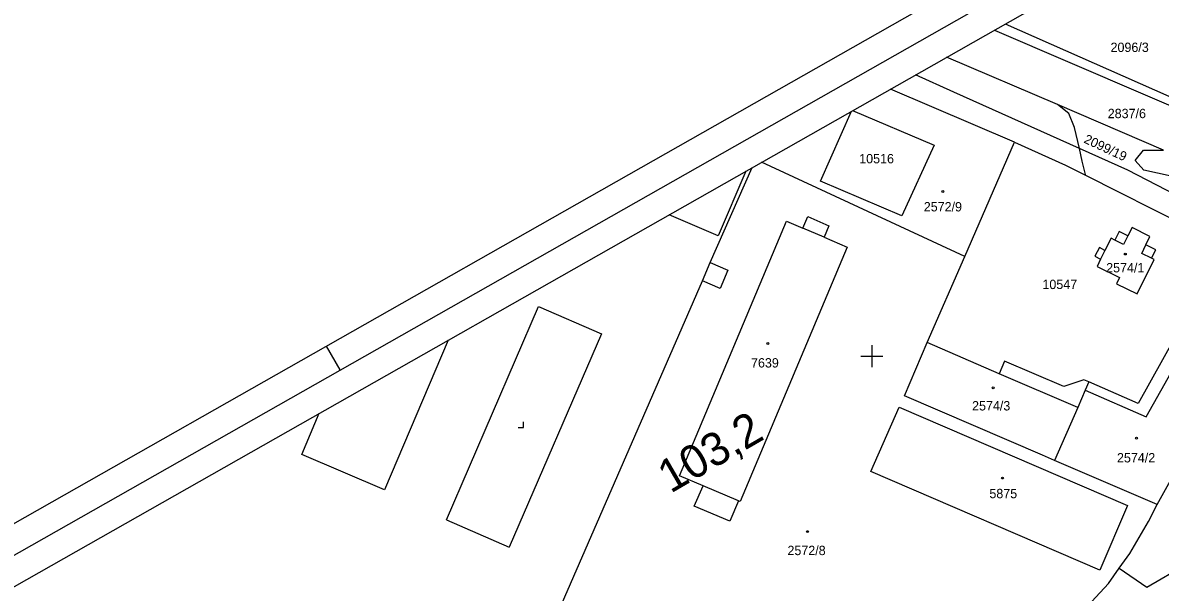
# Model space of a CAD drawing. Extents: x -566165 to -565287, y -1203064 to -1202391.
# Drawn here: x -565854.5 to -565647.5, y -1202643 to -1202539.4 of the extents above; entities that cross this region are included whole.
import ezdxf

# ---------------------------------------------------------------- set-up
doc = ezdxf.new("R2010")
doc.units = 0
for name, color, linetype in [('Hranice parcel', 7, 'Continuous'), ('Parcelní čísla', 7, 'Continuous'), ('Vnitřní kresba', 7, 'Continuous'), ('Vrstva 1', 7, 'Continuous'), ('Vrstva 5', 7, 'Continuous'), ('Vrstva 7', 7, 'Continuous'), ('Značky budov', 7, 'Continuous'), ('Značky kultur', 7, 'Continuous')]:
    doc.layers.add(name, color=color, linetype=linetype)

msp = doc.modelspace()

# ---------------------------------------------------------------- linework, layer by layer
at = {"layer": 'Hranice parcel'}
for p, q in [((-565675.68, -1202539.58), (-565645.92, -1202552.72)), ((-565674, -1202561.11), (-565696.58, -1202551.43)), ((-565662.2, -1202562.24), (-565685.03, -1202551.98)), ((-565646.9, -1202562.53), (-565666.21, -1202554.22)), ((-565709.33, -1202568.19), (-565703.68, -1202555.46)), ((-565662.2, -1202562.24), (-565663.08, -1202558.41)), ((-565683.07, -1202581.87), (-565674, -1202561.11)), ((-565674, -1202561.11), (-565664.72, -1202565.27)), ((-565661.67, -1202564.55), (-565662.2, -1202562.24)), ((-565653.37, -1202566.21), (-565662.2, -1202562.24)), ((-565683.07, -1202581.87), (-565720.05, -1202564.75)), ((-565729.37, -1202583), (-565721.74, -1202565.71)), ((-565722.89, -1202566.36), (-565727.95, -1202578.11)), ((-565664.72, -1202565.27), (-565661.08, -1202567.11)), ((-565661.08, -1202567.11), (-565661.11, -1202566.99)), ((-565626.76, -1202580.01), (-565653.37, -1202566.21)), ((-565661.08, -1202567.11), (-565633.3, -1202581.16)), ((-565689.92, -1202597.55), (-565683.07, -1202581.87)), ((-565649.94, -1202642), (-565590.75, -1202607.97)), ((-565648.07, -1202626.98), (-565641.33, -1202614.86)), ((-565666.73, -1202618.97), (-565668.89, -1202618.04)), ((-565648.07, -1202626.98), (-565666.73, -1202618.97)), ((-565654.95, -1202638.6), (-565653.02, -1202635.92)), ((-565656.92, -1202641.34), (-565654.95, -1202638.6)), ((-565654.95, -1202638.6), (-565649.94, -1202642))]:
    msp.add_line(p, q, dxfattribs=at)
for points in [[(-565677.65, -1202540.7), (-565636.53, -1202558.35)], [(-565666.21, -1202554.22), (-565686.4, -1202545.66)], [(-565685.03, -1202551.98), (-565692.02, -1202548.85)], [(-565663.08, -1202558.41), (-565664.13, -1202555.88), (-565666.21, -1202554.22)], [(-565703.5, -1202555.36), (-565688.64, -1202561.63), (-565694.52, -1202574.52), (-565709.33, -1202568.19)], [(-565611.48, -1202587.61), (-565606.37, -1202588.55), (-565605.02, -1202584.84), (-565609.5, -1202583.94), (-565619.91, -1202582.67), (-565618.87, -1202580.59), (-565643.02, -1202567.83), (-565650.49, -1202566.2), (-565652.02, -1202564.43), (-565650.55, -1202562.52), (-565646.9, -1202562.53)], [(-565661.11, -1202566.99), (-565661.23, -1202566.5), (-565661.67, -1202564.55)], [(-565727.95, -1202578.11), (-565736.87, -1202574.29)], [(-565715.53, -1202575.44), (-565712.53, -1202576.72), (-565711.64, -1202574.64), (-565707.77, -1202576.29), (-565708.67, -1202578.37), (-565704.44, -1202580.18), (-565723.91, -1202626.46), (-565724.22, -1202626.33), (-565725.81, -1202630.05), (-565732.28, -1202627.29), (-565730.69, -1202623.57), (-565734.96, -1202621.75), (-565715.53, -1202575.44)], [(-565658.99, -1202583.69), (-565654.89, -1202585.73), (-565655.44, -1202586.84), (-565651.71, -1202588.69), (-565648.61, -1202582.44), (-565649.07, -1202582.21), (-565648.3, -1202580.67), (-565650.11, -1202579.77), (-565649.38, -1202578.26), (-565652.62, -1202576.61), (-565653.38, -1202578.15), (-565654.99, -1202577.35), (-565655.76, -1202578.89), (-565656.44, -1202578.55), (-565657.54, -1202580.77)], [(-565633.3, -1202581.16), (-565640.46, -1202593.97), (-565642.65, -1202592.75), (-565651.52, -1202608.61), (-565660.47, -1202604.69)], [(-565657.54, -1202580.77), (-565658.57, -1202580.25), (-565659.37, -1202581.85), (-565658.33, -1202582.36), (-565658.99, -1202583.69)], [(-565758.54, -1202649.93), (-565730.78, -1202586.31), (-565729.37, -1202583)], [(-565777.1, -1202597.11), (-565788.65, -1202624.32), (-565803.71, -1202617.93), (-565800.53, -1202610.4)], [(-565668.89, -1202618.04), (-565694.05, -1202607.23), (-565689.92, -1202597.55)], [(-565675.81, -1202600.91), (-565676.8, -1202603.2), (-565689.92, -1202597.55)], [(-565660.47, -1202604.69), (-565661.37, -1202604.3), (-565665.05, -1202605.56), (-565675.81, -1202600.91)], [(-565660.47, -1202604.69), (-565661.13, -1202606.2), (-565662.51, -1202609.35), (-565666.73, -1202618.97)], [(-565700.13, -1202620.97), (-565695.02, -1202609.31), (-565653.44, -1202627.2)], [(-565653.44, -1202627.2), (-565658.48, -1202638.91), (-565700.13, -1202620.97)], [(-565653.02, -1202635.92), (-565649.64, -1202630.11), (-565648.07, -1202626.98)], [(-565674.56, -1202656.97), (-565671.65, -1202655.14), (-565668.84, -1202653.22), (-565663.79, -1202648.82), (-565656.92, -1202641.34)]]:
    msp.add_lwpolyline(points, dxfattribs=at)
at = {"layer": 'Vnitřní kresba'}
for p, q in [((-565708.67, -1202578.37), (-565712.53, -1202576.72)), ((-565654.15, -1202579.69), (-565655.76, -1202578.89)), ((-565653.38, -1202578.15), (-565654.15, -1202579.69)), ((-565657.54, -1202580.77), (-565658.33, -1202582.36)), ((-565650.86, -1202581.32), (-565650.11, -1202579.77)), ((-565649.07, -1202582.21), (-565650.86, -1202581.32)), ((-565729.37, -1202583), (-565726.16, -1202584.37)), ((-565726.16, -1202584.37), (-565727.57, -1202587.68)), ((-565727.57, -1202587.68), (-565730.78, -1202586.31)), ((-565777.39, -1202629.8), (-565760.61, -1202590.98)), ((-565760.61, -1202590.98), (-565749.16, -1202595.94)), ((-565749.16, -1202595.94), (-565765.95, -1202634.75)), ((-565650.02, -1202611.06), (-565640.46, -1202593.97)), ((-565662.51, -1202609.35), (-565676.8, -1202603.2)), ((-565661.13, -1202606.2), (-565650.02, -1202611.06)), ((-565724.22, -1202626.33), (-565730.69, -1202623.57)), ((-565777.39, -1202629.8), (-565765.95, -1202634.75))]:
    msp.add_line(p, q, dxfattribs=at)
at = {"layer": 'Vrstva 1'}
msp.add_line((-565796.76, -1202602.52), (-565799.23, -1202598.18), dxfattribs=at)
for points in [[(-566017.99, -1203063.73), (-565287.38, -1202649.25), (-565433.92, -1202390.94), (-566164.53, -1202805.42)], [(-565294.2, -1202647.37), (-566016.11, -1203056.92), (-566157.72, -1202807.3), (-565435.81, -1202397.75)], [(-566014.23, -1203050.11), (-565479.31, -1202746.65), (-565615.99, -1202505.72), (-566150.91, -1202809.18)]]:
    msp.add_lwpolyline(points, close=True, dxfattribs=at)
at = {"layer": 'Vrstva 5'}
for p, q in [((-565700, -1202598), (-565700, -1202602)), ((-565702, -1202600), (-565698, -1202600))]:
    msp.add_line(p, q, dxfattribs=at)
at = {"layer": 'Značky budov'}
for centre in [(-565687.03, -1202570.09), (-565653.84, -1202581.44), (-565718.89, -1202597.73), (-565677.91, -1202605.79), (-565651.79, -1202614.92), (-565676.21, -1202622.18), (-565711.68, -1202631.93)]:
    msp.add_circle(centre, 0.175, dxfattribs=at)
at = {"layer": 'Značky kultur'}
for p, q in [((-565763.36, -1202612.96), (-565763.36, -1202611.96)), ((-565764.36, -1202612.96), (-565763.36, -1202612.96))]:
    msp.add_line(p, q, dxfattribs=at)

# ---------------------------------------------------------------- texts
at = {"layer": 'Parcelní čísla'}
for s, p in [('2096/3', (-565656.53, -1202544.69)), ('2837/6', (-565657.04, -1202556.73)), ('10516', (-565702.27, -1202564.94)), ('2572/9', (-565690.52, -1202573.69)), ('2574/1', (-565657.33, -1202584.78)), ('10547', (-565668.93, -1202587.81)), ('7639', (-565721.96, -1202602.08)), ('2574/3', (-565681.73, -1202609.89)), ('2574/2', (-565655.36, -1202619.34)), ('5875', (-565678.58, -1202625.85)), ('2572/8', (-565715.33, -1202636.2))]:
    msp.add_text(s, height=1.7, dxfattribs=at).set_placement(p)
msp.add_text('2099/19', height=1.7, rotation=335, dxfattribs=at).set_placement((-565661.52, -1202561.13))
at = {"layer": 'Vrstva 7'}
msp.add_text('103,2', height=6, rotation=30.147, dxfattribs=at).set_placement((-565736.62, -1202625.06))

doc.saveas('drawing.dxf')
